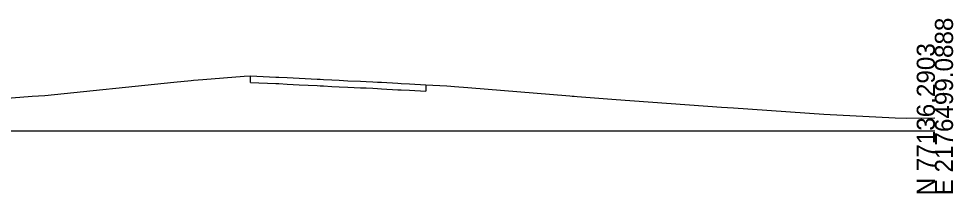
# Model space of a CAD drawing. Extents: x 2207892 to 2209721, y 61220 to 65449.
# Drawn here: x 2208176.8 to 2208321, y 61397.6 to 61424.6 of the extents above; entities that cross this region are included whole.
import ezdxf

# ---------------------------------------------------------------- set-up
doc = ezdxf.new("R2010")
doc.units = 0
for name, color, linetype in [('Exist DTM Drainline Cogo Comment', 7, 'Continuous'), ('Exist Roads EOP Other Cogo Elevation', 7, 'Continuous'), ('Exist Roads EOP Other Cogo Number', 7, 'Continuous')]:
    doc.layers.add(name, color=color, linetype=linetype)

msp = doc.modelspace()

# ---------------------------------------------------------------- linework, layer by layer
at = {"layer": 'Exist DTM Drainline Cogo Comment'}
for p, q in [((2208212.56, 61414.77), (2208212.56, 61415.77)), ((2208212.56, 61414.77), (2208216.46, 61414.6)), ((2208216.46, 61414.6), (2208216.9, 61414.58)), ((2208216.9, 61414.58), (2208218.22, 61414.51)), ((2208218.22, 61414.51), (2208220.04, 61414.41)), ((2208220.04, 61414.41), (2208222.84, 61414.27)), ((2208222.84, 61414.27), (2208223.29, 61414.25)), ((2208223.29, 61414.25), (2208223.79, 61414.23)), ((2208223.79, 61414.23), (2208225.09, 61414.16)), ((2208225.09, 61414.16), (2208226.23, 61414.11)), ((2208226.23, 61414.11), (2208227.58, 61414.04)), ((2208227.58, 61414.04), (2208229.54, 61413.95)), ((2208229.54, 61413.95), (2208230.41, 61413.91)), ((2208230.41, 61413.91), (2208231.42, 61413.86)), ((2208231.42, 61413.86), (2208232.17, 61413.82)), ((2208232.17, 61413.82), (2208232.78, 61413.79)), ((2208232.78, 61413.79), (2208235.3, 61413.64)), ((2208235.3, 61413.64), (2208235.82, 61413.62)), ((2208235.82, 61413.62), (2208237.08, 61413.55)), ((2208237.08, 61413.55), (2208239.61, 61413.42)), ((2208239.61, 61414.42), (2208239.61, 61413.42)), ((2208239.61, 61413.42), (2208239.61, 61413.42))]:
    msp.add_line(p, q, dxfattribs=at)
at = {"layer": 'Exist Roads EOP Other Cogo Elevation'}
msp.add_lwpolyline([(2208173.02, 61412.16), (2208178.84, 61412.63), (2208180.8, 61412.77), (2208200.74, 61414.81), (2208203.41, 61415.09), (2208203.73, 61415.11), (2208205.19, 61415.23), (2208211.58, 61415.72), (2208212.56, 61415.77), (2208216.46, 61415.6), (2208216.9, 61415.58), (2208218.22, 61415.51), (2208220.04, 61415.41), (2208222.84, 61415.27), (2208223.29, 61415.25), (2208223.79, 61415.23), (2208225.09, 61415.16), (2208226.23, 61415.11), (2208227.58, 61415.04), (2208229.54, 61414.95), (2208230.41, 61414.91), (2208231.42, 61414.86), (2208232.17, 61414.82), (2208232.78, 61414.79), (2208235.3, 61414.64), (2208235.82, 61414.62), (2208237.08, 61414.55), (2208239.61, 61414.42), (2208242.86, 61414.22), (2208243.45, 61414.19), (2208244.02, 61414.16), (2208246.08, 61413.99), (2208261.85, 61412.69), (2208262.21, 61412.65), (2208262.52, 61412.62), (2208262.98, 61412.58), (2208268.98, 61412.15), (2208285.23, 61410.96), (2208287.1, 61410.82), (2208301.03, 61409.84), (2208312.03, 61409.32), (2208313.82, 61409.22), (2208318.17, 61409.29)], dxfattribs=at)
at = {"layer": 'Exist Roads EOP Other Cogo Number'}
msp.add_line((2208118.17, 61407.31), (2208318.17, 61407.31), dxfattribs=at)

# ---------------------------------------------------------------- texts
for s, p in [('E 2176499.0888', (2208320.97, 61397.31)), ('N 77136.2903', (2208318.17, 61397.31))]:
    msp.add_text(s, height=2.8, rotation=90, dxfattribs=at).set_placement(p)

doc.saveas('drawing.dxf')
